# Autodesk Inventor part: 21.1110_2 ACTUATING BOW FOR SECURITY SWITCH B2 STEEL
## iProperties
Created: 2007-05
Part Number: 21.1110_2 ACTUATING BOW FOR SECURITY SWITCH B2 STEEL
Document SubType Name: Modeling
Designer: Andy Moles
Material: Steel
Mass: 6.04983 g
Surface Area: 12.3651 cm^2
Volume: 0.770679 cm^3
Density: 7.85 g/cm^3
Author: Andy Moles
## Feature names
1. Extrusion1
